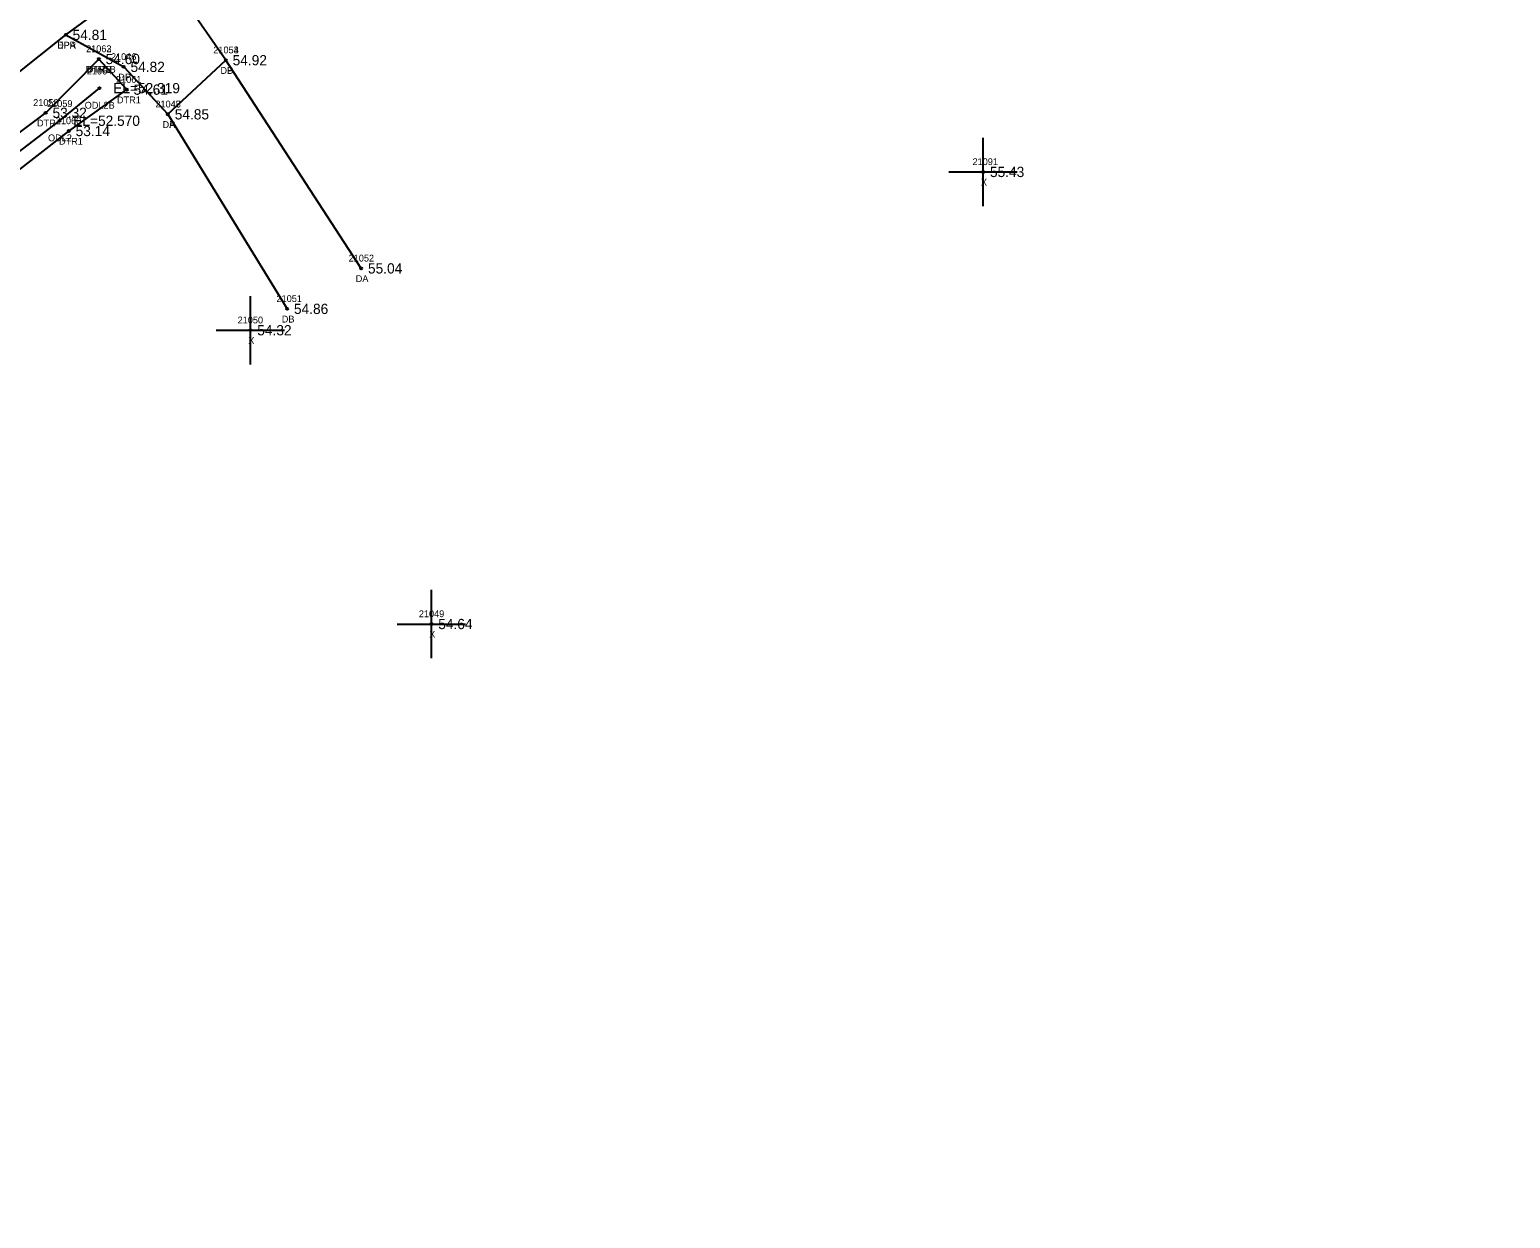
# Model space of a CAD drawing. Extents: x 2420351 to 2422725, y 845330 to 846558.
# Drawn here: x 2422224.3 to 2422440.9, y 845960.9 to 846134.8 of the extents above; entities that cross this region are included whole.
import ezdxf

# ---------------------------------------------------------------- set-up
doc = ezdxf.new("R2010")
doc.units = 0
for name, color, linetype in [('RD_EX_Driveway', 7, 'Continuous'), ('RD_EX_Driveway_txCode', 7, 'Continuous'), ('RD_EX_H2O', 7, 'Continuous'), ('RD_EX_H2O_txCode', 7, 'Continuous'), ('RD_EX_Misc', 7, 'Continuous'), ('RD_EX_Misc_txCode', 7, 'Continuous'), ('RD_EX_Road', 7, 'Continuous'), ('RD_EX_Road_txCode', 7, 'Continuous'), ('RD_EX_TX_Driveway_ELEV', 7, 'Continuous'), ('RD_EX_TX_H2O_ELEV', 7, 'Continuous'), ('RD_EX_TX_Misc_ELEV', 7, 'Continuous'), ('RD_EX_TX_Road_ELEV', 7, 'Continuous'), ('RD_SMD_Locator', 7, 'Continuous')]:
    doc.layers.add(name, color=color, linetype=linetype)

msp = doc.modelspace()

# ---------------------------------------------------------------- linework, layer by layer
at = {"layer": 'RD_EX_Driveway'}
for p, q in [((2422272.76, 846099.87), (2422252.96, 846130.33)), ((2422244.49, 846122.41), (2422261.93, 846093.95))]:
    msp.add_line(p, q, dxfattribs=at)
msp.add_lwpolyline([(2422229.55, 846134.03), (2422238.02, 846129.35), (2422244.49, 846122.41), (2422252.96, 846130.33), (2422246.61, 846139.51), (2422245.4, 846145.63)], dxfattribs=at)
at = {"layer": 'RD_EX_H2O'}
for points in [[(2422041.57, 845964.03), (2422050.29, 845973.48), (2422074.85, 845997.99), (2422081.34, 846008.26), (2422156.01, 846069.78), (2422226.61, 846122.63), (2422234.38, 846130.5)], [(2422041.57, 845964.03), (2422052.74, 845970.26), (2422079.02, 845992.82), (2422087.11, 846004.78), (2422160.41, 846065.75), (2422229.99, 846119.97), (2422238.47, 846126.02), (2422234.38, 846130.5)], [(2422041.57, 845964.03), (2422051.27, 845971.9), (2422076.82, 845995.47), (2422084.64, 846006.08), (2422158.42, 846067.72), (2422228.64, 846121.47), (2422234.49, 846126.24)]]:
    msp.add_lwpolyline(points, dxfattribs=at)
at = {"layer": 'RD_EX_Misc'}
for p, q in [((2422363.75, 846108.98), (2422363.75, 846118.98)), ((2422358.75, 846113.98), (2422368.75, 846113.98)), ((2422256.56, 846085.82), (2422256.56, 846095.82)), ((2422251.56, 846090.82), (2422261.56, 846090.82)), ((2422283.04, 846042.84), (2422283.04, 846052.84)), ((2422278.04, 846047.84), (2422288.04, 846047.84))]:
    msp.add_line(p, q, dxfattribs=at)
at = {"layer": 'RD_EX_Road'}
msp.add_lwpolyline([(2421810.77, 845819.82), (2421865.31, 845853.52), (2421953.26, 845916.07), (2421995.06, 845948.03), (2422068.36, 846005.98), (2422153.46, 846073.36), (2422229.55, 846134.03), (2422245.4, 846145.63), (2422297.08, 846186.88), (2422369.77, 846243.69), (2422382.04, 846253.08), (2422449.02, 846305.97), (2422517.14, 846360.1), (2422592.58, 846419.1), (2422657.51, 846470.1)], dxfattribs=at)
at = {"layer": 'RD_SMD_Locator'}
for centre in [(2422229.55, 846134.03), (2422229.55, 846134.03), (2422234.38, 846130.5), (2422234.38, 846130.5), (2422252.96, 846130.33), (2422252.96, 846130.33), (2422238.02, 846129.35), (2422234.49, 846126.24), (2422238.47, 846126.02), (2422226.61, 846122.63), (2422228.64, 846121.47), (2422244.49, 846122.41), (2422244.49, 846122.41), (2422229.99, 846119.97), (2422363.75, 846113.98), (2422272.76, 846099.87), (2422261.93, 846093.95), (2422256.56, 846090.82), (2422283.04, 846047.84)]:
    msp.add_circle(centre, 0.15, dxfattribs=at)

# ---------------------------------------------------------------- texts
at = {"layer": 'RD_EX_Driveway_txCode'}
for s, p in [('DPA', (2422228.28, 846132.03)), ('21053', (2422251.13, 846131.33)), ('21054', (2422251.13, 846131.33)), ('21046', (2422236.16, 846130.35)), ('DP', (2422237.24, 846127.35)), ('DP', (2422252.18, 846128.33)), ('DB', (2422252.18, 846128.33)), ('21047', (2422242.66, 846123.41)), ('21048', (2422242.66, 846123.41)), ('DA', (2422243.7, 846120.41)), ('DP', (2422243.71, 846120.41)), ('21052', (2422270.93, 846100.87)), ('DA', (2422271.97, 846097.87)), ('21051', (2422260.38, 846094.95)), ('DB', (2422261.15, 846091.95))]:
    msp.add_text(s, height=1, dxfattribs=at).set_placement(p)
at = {"layer": 'RD_EX_H2O_txCode'}
for s, p in [('21062', (2422232.52, 846131.5)), ('21063', (2422232.52, 846131.5)), ('DTR1B', (2422232.47, 846128.5)), ('21064', (2422232.63, 846128.24)), ('DTRB', (2422232.64, 846128.5)), ('21061', (2422236.9, 846127.02)), ('21058', (2422224.78, 846123.63)), ('21059', (2422226.81, 846123.47)), ('ODL2B', (2422232.32, 846123.24)), ('DTR1', (2422237.04, 846124.02)), ('DTR', (2422225.34, 846120.63)), ('21060', (2422228.09, 846120.97)), ('ODL2', (2422226.95, 846118.47)), ('DTR1', (2422228.56, 846117.97))]:
    msp.add_text(s, height=1, dxfattribs=at).set_placement(p)
at = {"layer": 'RD_EX_Misc_txCode'}
for s, p in [('21091', (2422362.2, 846114.98)), ('X', (2422363.43, 846111.98)), ('21050', (2422254.69, 846091.82)), ('X', (2422256.25, 846088.82)), ('21049', (2422281.2, 846048.84)), ('X', (2422282.72, 846045.84))]:
    msp.add_text(s, height=1, dxfattribs=at).set_placement(p)
at = {"layer": 'RD_EX_Road_txCode'}
msp.add_text('EPR', height=1, dxfattribs=at).set_placement((2422228.32, 846132.03))
at = {"layer": 'RD_EX_TX_Driveway_ELEV'}
for s, p in [('54.81', (2422230.55, 846133.28)), ('54.82', (2422239.02, 846128.6)), ('54.92', (2422253.96, 846129.58)), ('54.92', (2422253.96, 846129.58)), ('54.85', (2422245.49, 846121.66)), ('54.85', (2422245.49, 846121.66)), ('55.04', (2422273.76, 846099.12)), ('54.86', (2422262.93, 846093.2))]:
    msp.add_text(s, height=1.5, dxfattribs=at).set_placement(p)
at = {"layer": 'RD_EX_TX_H2O_ELEV'}
for s, p in [('54.60', (2422235.38, 846129.75)), ('54.60', (2422235.38, 846129.75)), ('EL=52.319', (2422236.49, 846125.49)), ('54.61', (2422239.47, 846125.27)), ('53.32', (2422227.61, 846121.88)), ('EL=52.570', (2422230.64, 846120.72)), ('53.14', (2422230.99, 846119.22))]:
    msp.add_text(s, height=1.5, dxfattribs=at).set_placement(p)
at = {"layer": 'RD_EX_TX_Misc_ELEV'}
for s, p in [('55.43', (2422364.75, 846113.23)), ('54.32', (2422257.56, 846090.07)), ('54.64', (2422284.04, 846047.09))]:
    msp.add_text(s, height=1.5, dxfattribs=at).set_placement(p)
at = {"layer": 'RD_EX_TX_Road_ELEV'}
msp.add_text('54.81', height=1.5, dxfattribs=at).set_placement((2422230.55, 846133.28))

doc.saveas('drawing.dxf')
